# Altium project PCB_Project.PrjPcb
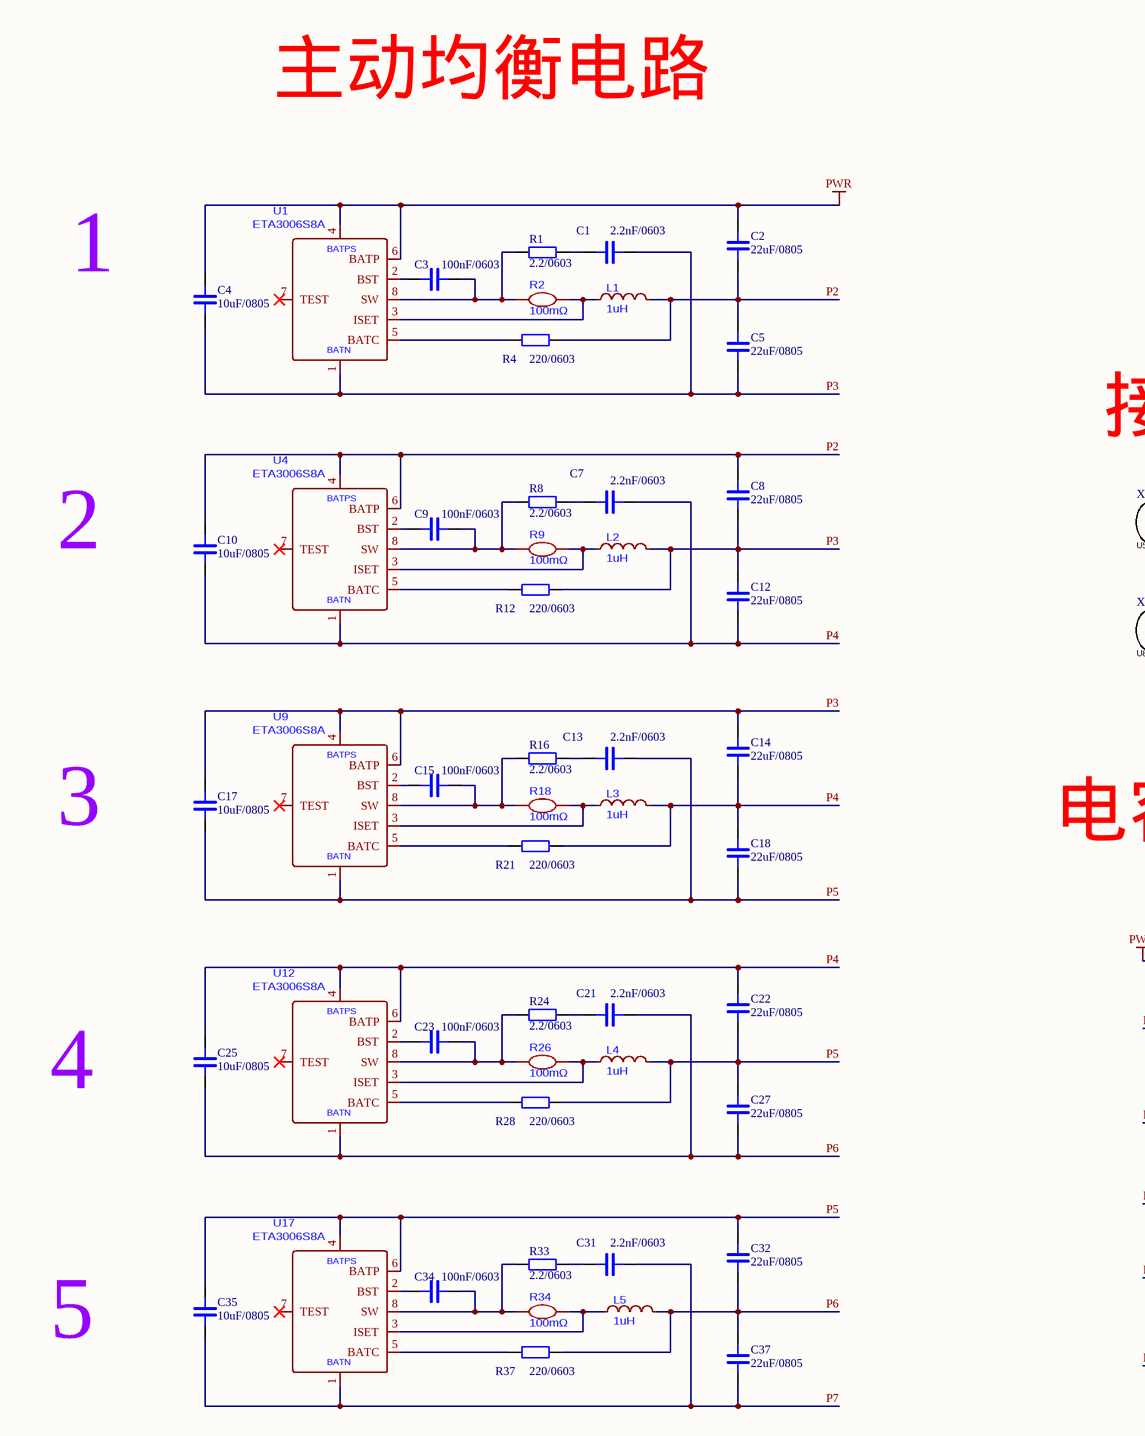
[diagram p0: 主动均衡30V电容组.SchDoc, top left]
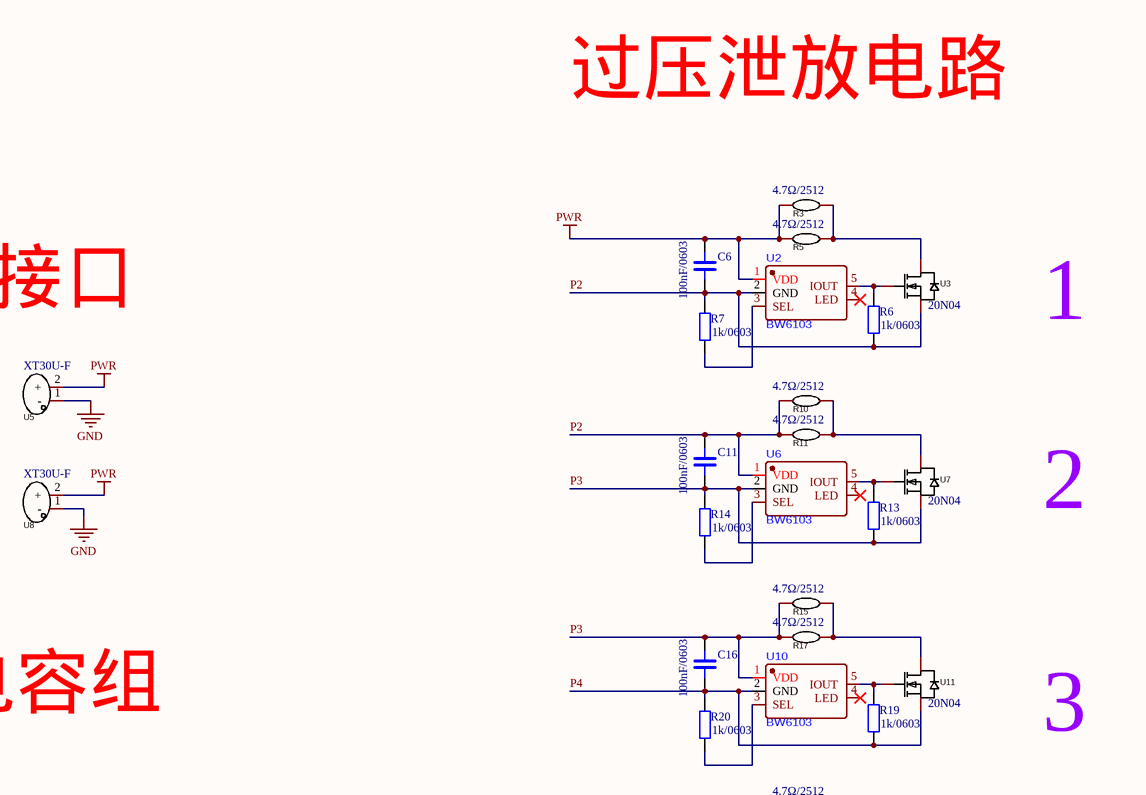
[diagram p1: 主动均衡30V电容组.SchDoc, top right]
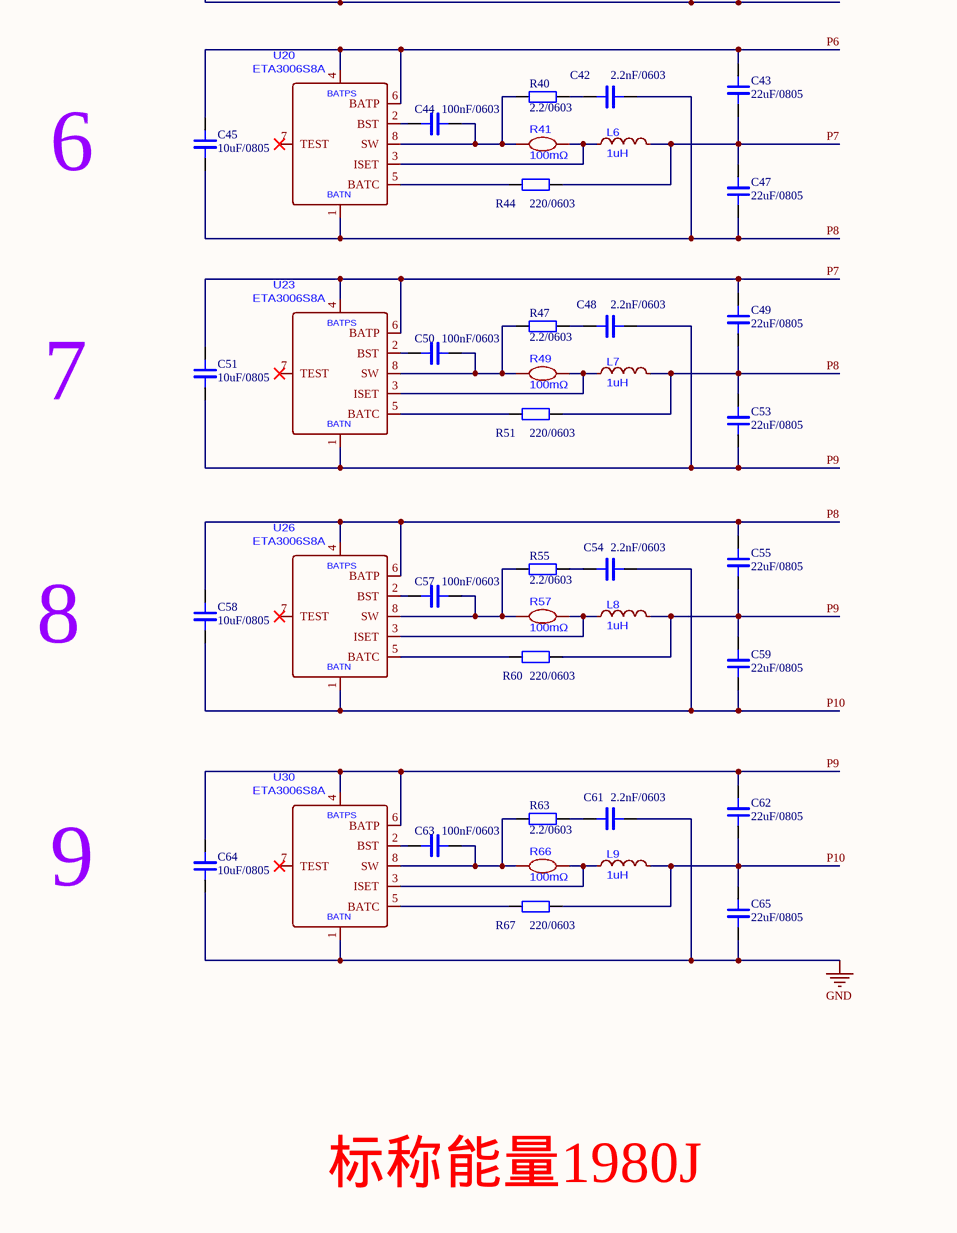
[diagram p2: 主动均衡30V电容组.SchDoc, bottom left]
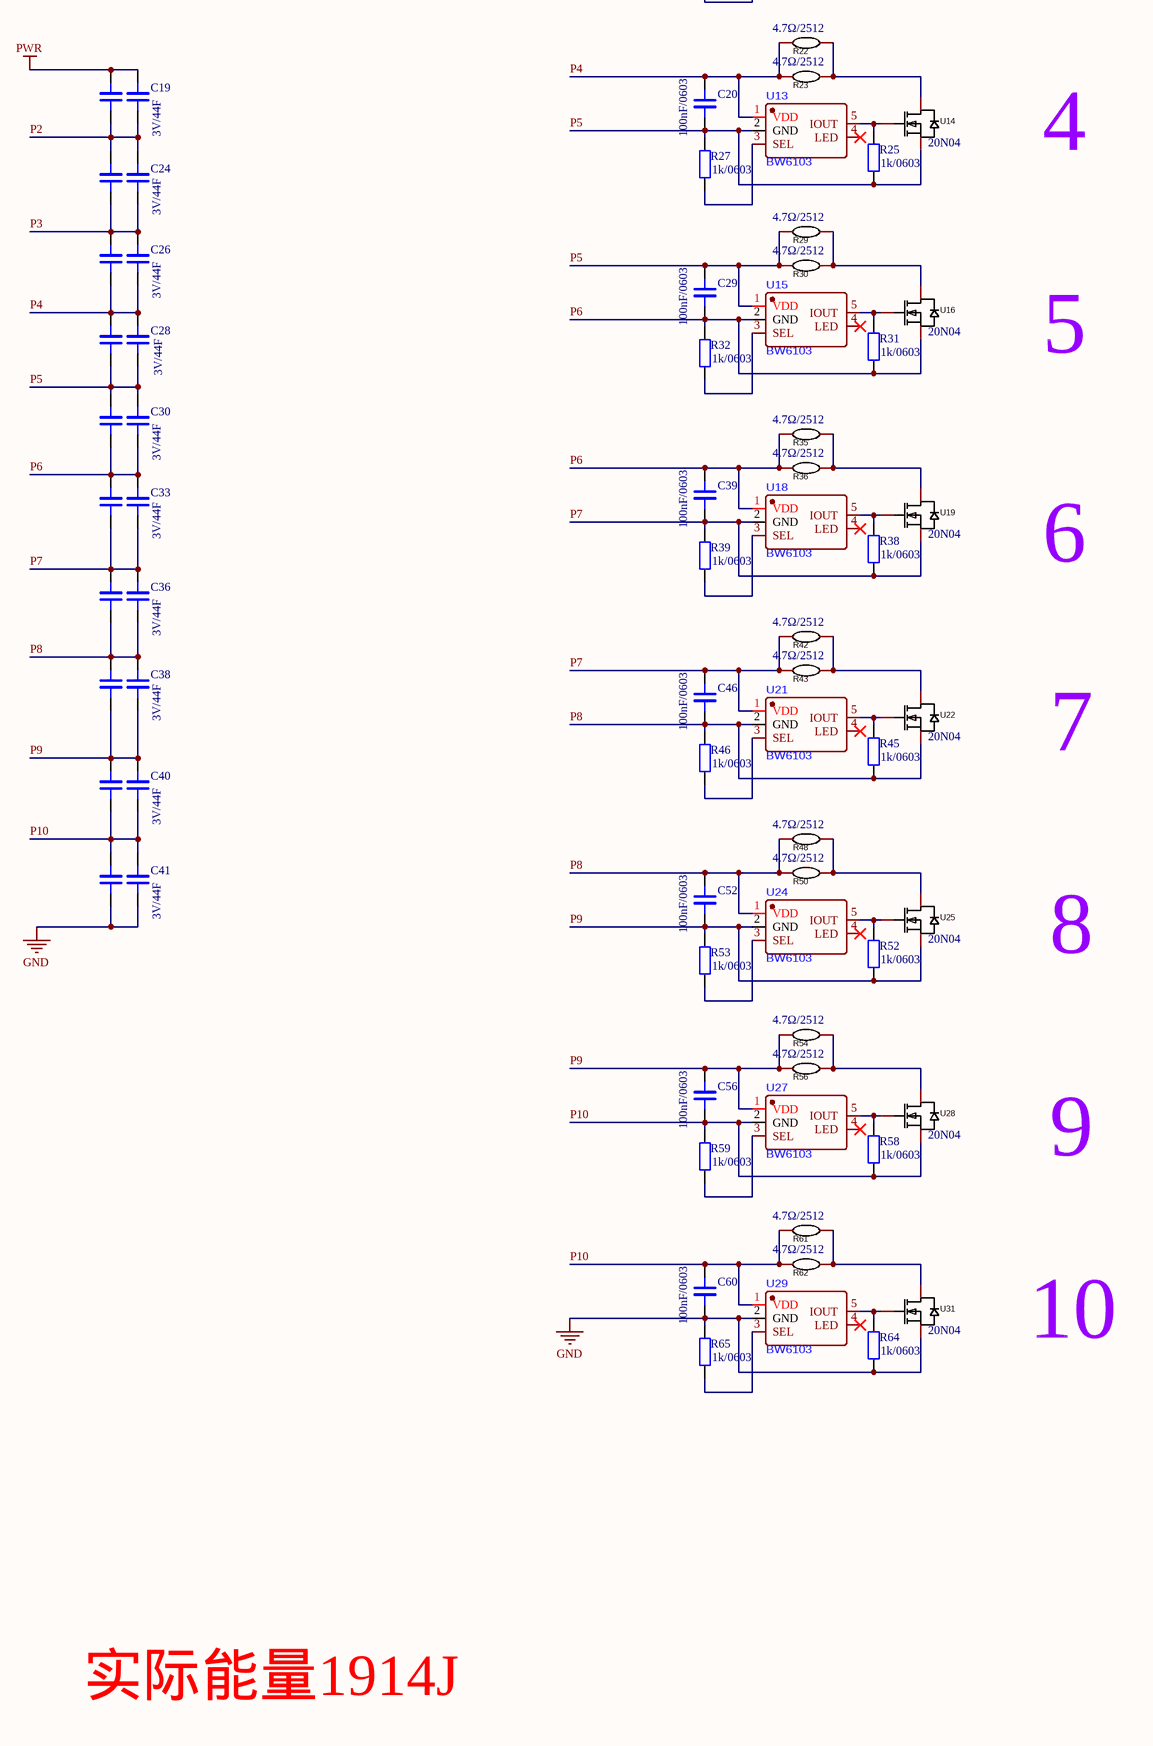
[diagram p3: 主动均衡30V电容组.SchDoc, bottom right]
1 sheet, 172 parts. Net scope: global (net labels, ports and power ports of the same name join across sheets).
Board file: PCB.PcbDoc

## Sheet 主动均衡30V电容组.SchDoc
size A1; SheetNumber: 1; SheetTotal: 1

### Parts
C1  2.2nF/0603  [C 0603_L]
C2  22uF/0805  [C 0805_L]
C3  100nF/0603  [C 0603_L]
C4  10uF/0805  [C 0805_L]
C5  22uF/0805  [C 0805_L]
C6  100nF/0603  [C 0603_L]
C7  2.2nF/0603  [C 0603_L]
C8  22uF/0805  [C 0805_L]
C9  100nF/0603  [C 0603_L]
C10  10uF/0805  [C 0805_L]
C11  100nF/0603  [C 0603_L]
C12  22uF/0805  [C 0805_L]
C13  2.2nF/0603  [C 0603_L]
C14  22uF/0805  [C 0805_L]
C15  100nF/0603  [C 0603_L]
C16  100nF/0603  [C 0603_L]
C17  10uF/0805  [C 0805_L]
C18  22uF/0805  [C 0805_L]
C19  3V/44F  [cap]
C20  100nF/0603  [C 0603_L]
C21  2.2nF/0603  [C 0603_L]
C22  22uF/0805  [C 0805_L]
C23  100nF/0603  [C 0603_L]
C24  3V/44F  [cap]
C25  10uF/0805  [C 0805_L]
C26  3V/44F  [cap]
C27  22uF/0805  [C 0805_L]
C28  3V/44F  [cap]
C29  100nF/0603  [C 0603_L]
C30  3V/44F  [cap]
C31  2.2nF/0603  [C 0603_L]
C32  22uF/0805  [C 0805_L]
C33  3V/44F  [cap]
C34  100nF/0603  [C 0603_L]
C35  10uF/0805  [C 0805_L]
C36  3V/44F  [cap]
C37  22uF/0805  [C 0805_L]
C38  3V/44F  [cap]
C39  100nF/0603  [C 0603_L]
C40  3V/44F  [cap]
C41  3V/44F  [cap]
C42  2.2nF/0603  [C 0603_L]
C43  22uF/0805  [C 0805_L]
C44  100nF/0603  [C 0603_L]
C45  10uF/0805  [C 0805_L]
C46  100nF/0603  [C 0603_L]
C47  22uF/0805  [C 0805_L]
C48  2.2nF/0603  [C 0603_L]
C49  22uF/0805  [C 0805_L]
C50  100nF/0603  [C 0603_L]
C51  10uF/0805  [C 0805_L]
C52  100nF/0603  [C 0603_L]
C53  22uF/0805  [C 0805_L]
C54  2.2nF/0603  [C 0603_L]
C55  22uF/0805  [C 0805_L]
C56  100nF/0603  [C 0603_L]
C57  100nF/0603  [C 0603_L]
C58  10uF/0805  [C 0805_L]
C59  22uF/0805  [C 0805_L]
C60  100nF/0603  [C 0603_L]
C61  2.2nF/0603  [C 0603_L]
C62  22uF/0805  [C 0805_L]
C63  100nF/0603  [C 0603_L]
C64  10uF/0805  [C 0805_L]
C65  22uF/0805  [C 0805_L]
L1  1uH  [IND-SMD_L4.4-W4.2]
L2  1uH  [IND-SMD_L4.4-W4.2]
L3  1uH  [IND-SMD_L4.4-W4.2]
L4  1uH  [IND-SMD_L4.4-W4.2]
L5  1uH  [IND-SMD_L4.4-W4.2]
L6  1uH  [IND-SMD_L4.4-W4.2]
L7  1uH  [IND-SMD_L4.4-W4.2]
L8  1uH  [IND-SMD_L4.4-W4.2]
L9  1uH  [IND-SMD_L4.4-W4.2]
R1  2.2/0603  [R 0603_L]
R2  100mΩ  [RES-SMD_L6.4-W3.2-R2512]
R3  4.7Ω/2512  [R2512]
R4  220/0603  [R 0603_L]
R5  4.7Ω/2512  [R2512]
R6  1k/0603  [R 0603_L]
R7  1k/0603  [R 0603_L]
R8  2.2/0603  [R 0603_L]
R9  100mΩ  [RES-SMD_L6.4-W3.2-R2512]
R10  4.7Ω/2512  [R2512]
R11  4.7Ω/2512  [R2512]
R12  220/0603  [R 0603_L]
R13  1k/0603  [R 0603_L]
R14  1k/0603  [R 0603_L]
R15  4.7Ω/2512  [R2512]
R16  2.2/0603  [R 0603_L]
R17  4.7Ω/2512  [R2512]
R18  100mΩ  [RES-SMD_L6.4-W3.2-R2512]
R19  1k/0603  [R 0603_L]
R20  1k/0603  [R 0603_L]
R21  220/0603  [R 0603_L]
R22  4.7Ω/2512  [R2512]
R23  4.7Ω/2512  [R2512]
R24  2.2/0603  [R 0603_L]
R25  1k/0603  [R 0603_L]
R26  100mΩ  [RES-SMD_L6.4-W3.2-R2512]
R27  1k/0603  [R 0603_L]
R28  220/0603  [R 0603_L]
R29  4.7Ω/2512  [R2512]
R30  4.7Ω/2512  [R2512]
R31  1k/0603  [R 0603_L]
R32  1k/0603  [R 0603_L]
R33  2.2/0603  [R 0603_L]
R34  100mΩ  [RES-SMD_L6.4-W3.2-R2512]
R35  4.7Ω/2512  [R2512]
R36  4.7Ω/2512  [R2512]
R37  220/0603  [R 0603_L]
R38  1k/0603  [R 0603_L]
R39  1k/0603  [R 0603_L]
R40  2.2/0603  [R 0603_L]
R41  100mΩ  [RES-SMD_L6.4-W3.2-R2512]
R42  4.7Ω/2512  [R2512]
R43  4.7Ω/2512  [R2512]
R44  220/0603  [R 0603_L]
R45  1k/0603  [R 0603_L]
R46  1k/0603  [R 0603_L]
R47  2.2/0603  [R 0603_L]
R48  4.7Ω/2512  [R2512]
R49  100mΩ  [RES-SMD_L6.4-W3.2-R2512]
R50  4.7Ω/2512  [R2512]
R51  220/0603  [R 0603_L]
R52  1k/0603  [R 0603_L]
R53  1k/0603  [R 0603_L]
R54  4.7Ω/2512  [R2512]
R55  2.2/0603  [R 0603_L]
R56  4.7Ω/2512  [R2512]
R57  100mΩ  [RES-SMD_L6.4-W3.2-R2512]
R58  1k/0603  [R 0603_L]
R59  1k/0603  [R 0603_L]
R60  220/0603  [R 0603_L]
R61  4.7Ω/2512  [R2512]
R62  4.7Ω/2512  [R2512]
R63  2.2/0603  [R 0603_L]
R64  1k/0603  [R 0603_L]
R65  1k/0603  [R 0603_L]
R66  100mΩ  [RES-SMD_L6.4-W3.2-R2512]
R67  220/0603  [R 0603_L]
U1  ETA3006S8A  [SOIC-8_L5.0-W4.0-P1.27-LS6.0-TL]
U2  BW6103  [TSOT-23-5_L2.9-W1.6-P0.95-LS2.8-BL]
U3  20N04  [TO-252-2_L6.6-W6.1-P4.57-LS9.9-BR-CW]
U4  ETA3006S8A  [SOIC-8_L5.0-W4.0-P1.27-LS6.0-TL]
U5  XT30U-F  [CONN-TH_XT30U-F]
U6  BW6103  [TSOT-23-5_L2.9-W1.6-P0.95-LS2.8-BL]
U7  20N04  [TO-252-2_L6.6-W6.1-P4.57-LS9.9-BR-CW]
U8  XT30U-F  [CONN-TH_XT30U-F]
U9  ETA3006S8A  [SOIC-8_L5.0-W4.0-P1.27-LS6.0-TL]
U10  BW6103  [TSOT-23-5_L2.9-W1.6-P0.95-LS2.8-BL]
U11  20N04  [TO-252-2_L6.6-W6.1-P4.57-LS9.9-BR-CW]
U12  ETA3006S8A  [SOIC-8_L5.0-W4.0-P1.27-LS6.0-TL]
U13  BW6103  [TSOT-23-5_L2.9-W1.6-P0.95-LS2.8-BL]
U14  20N04  [TO-252-2_L6.6-W6.1-P4.57-LS9.9-BR-CW]
U15  BW6103  [TSOT-23-5_L2.9-W1.6-P0.95-LS2.8-BL]
U16  20N04  [TO-252-2_L6.6-W6.1-P4.57-LS9.9-BR-CW]
U17  ETA3006S8A  [SOIC-8_L5.0-W4.0-P1.27-LS6.0-TL]
U18  BW6103  [TSOT-23-5_L2.9-W1.6-P0.95-LS2.8-BL]
U19  20N04  [TO-252-2_L6.6-W6.1-P4.57-LS9.9-BR-CW]
U20  ETA3006S8A  [SOIC-8_L5.0-W4.0-P1.27-LS6.0-TL]
U21  BW6103  [TSOT-23-5_L2.9-W1.6-P0.95-LS2.8-BL]
U22  20N04  [TO-252-2_L6.6-W6.1-P4.57-LS9.9-BR-CW]
U23  ETA3006S8A  [SOIC-8_L5.0-W4.0-P1.27-LS6.0-TL]
U24  BW6103  [TSOT-23-5_L2.9-W1.6-P0.95-LS2.8-BL]
U25  20N04  [TO-252-2_L6.6-W6.1-P4.57-LS9.9-BR-CW]
U26  ETA3006S8A  [SOIC-8_L5.0-W4.0-P1.27-LS6.0-TL]
U27  BW6103  [TSOT-23-5_L2.9-W1.6-P0.95-LS2.8-BL]
U28  20N04  [TO-252-2_L6.6-W6.1-P4.57-LS9.9-BR-CW]
U29  BW6103  [TSOT-23-5_L2.9-W1.6-P0.95-LS2.8-BL]
U30  ETA3006S8A  [SOIC-8_L5.0-W4.0-P1.27-LS6.0-TL]
U31  20N04  [TO-252-2_L6.6-W6.1-P4.57-LS9.9-BR-CW]

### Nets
GND: C41.1 C41.3 C60.2 C61.1 C64.2 C65.2 R64.2 R65.1 U5.1(-) U8.1(-) U29.2(GND) U30.1(BATC) U31.3(S)
PWR: C2.1 C4.1 C6.1 C19.1 C19.3 R3.1 R5.1 U1.4(BATPS) U1.6(BATP) U2.1(VDD) U5.2(+) U8.2(+)
P2: C2.2 C5.1 C6.2 C8.1 C10.1 C11.1 C19.2 C19.4 C24.2 C24.4 L1.2 R4.2 R6.2 R7.1 R10.1 R11.1 U2.2(GND) U3.3(S) U4.4(BATPS) U4.6(BATP) U6.1(VDD)
P3: C1.1 C4.2 C5.2 C8.2 C11.2 C12.1 C14.1 C16.1 C17.1 C24.1 C24.3 C26.1 C26.3 L2.2 R12.2 R13.2 R14.1 R15.1 R17.1 U1.1(BATC) U6.2(GND) U7.3(S) U9.4(BATPS) U9.6(BATP) U10.1(VDD)
P4: C7.1 C10.2 C12.2 C14.2 C16.2 C18.1 C20.1 C22.1 C25.1 C26.2 C26.4 C28.2 C28.4 L3.2 R19.2 R20.1 R21.2 R22.1 R23.1 U4.1(BATC) U10.2(GND) U11.3(S) U12.4(BATPS) U12.6(BATP) U13.1(VDD)
P5: C13.1 C17.2 C18.2 C20.2 C22.2 C27.1 C28.1 C28.3 C29.1 C30.1 C30.3 C32.1 C35.1 L4.2 R25.2 R27.1 R28.2 R29.1 R30.1 U9.1(BATC) U13.2(GND) U14.3(S) U15.1(VDD) U17.4(BATPS) U17.6(BATP)
P6: C21.1 C25.2 C27.2 C29.2 C30.2 C30.4 C32.2 C33.2 C33.4 C37.1 C39.1 C43.1 C45.1 L5.2 R31.2 R32.1 R35.1 R36.1 R37.2 U12.1(BATC) U15.2(GND) U16.3(S) U18.1(VDD) U20.4(BATPS) U20.6(BATP)
P7: C31.1 C33.1 C33.3 C35.2 C36.1 C36.3 C37.2 C39.2 C43.2 C46.1 C47.1 C49.1 C51.1 L6.2 R38.2 R39.1 R42.1 R43.1 R44.2 U17.1(BATC) U18.2(GND) U19.3(S) U21.1(VDD) U23.4(BATPS) U23.6(BATP)
P8: C36.2 C36.4 C38.2 C38.4 C42.1 C45.2 C46.2 C47.2 C49.2 C52.1 C53.1 C55.1 C58.1 L7.2 R45.2 R46.1 R48.1 R50.1 R51.2 U20.1(BATC) U21.2(GND) U22.3(S) U24.1(VDD) U26.4(BATPS) U26.6(BATP)
P9: C38.1 C38.3 C40.1 C40.3 C48.1 C51.2 C52.2 C53.2 C55.2 C56.1 C59.1 C62.1 C64.1 L8.2 R52.2 R53.1 R54.1 R56.1 R60.2 U23.1(BATC) U24.2(GND) U25.3(S) U27.1(VDD) U30.4(BATPS) U30.6(BATP)
P10: C40.2 C40.4 C41.2 C41.4 C54.1 C56.2 C58.2 C59.2 C60.1 C62.2 C65.1 L9.2 R58.2 R59.1 R61.1 R62.1 R67.2 U26.1(BATC) U27.2(GND) U28.3(S) U29.1(VDD)
NetC1_2: C1.2 R1.2
NetC3_1: C3.1 R1.1 R2.1 U1.8(SW)
NetC3_2: C3.2 U1.2(BST)
NetC7_2: C7.2 R8.2
NetC9_1: C9.1 R8.1 R9.1 U4.8(SW)
NetC9_2: C9.2 U4.2(BST)
NetC13_2: C13.2 R16.2
NetC15_1: C15.1 R16.1 R18.1 U9.8(SW)
NetC15_2: C15.2 U9.2(BST)
NetC21_2: C21.2 R24.2
NetC23_1: C23.1 R24.1 R26.1 U12.8(SW)
NetC23_2: C23.2 U12.2(BST)
NetC31_2: C31.2 R33.2
NetC34_1: C34.1 R33.1 R34.1 U17.8(SW)
NetC34_2: C34.2 U17.2(BST)
NetC42_2: C42.2 R40.2
NetC44_1: C44.1 R40.1 R41.1 U20.8(SW)
NetC44_2: C44.2 U20.2(BST)
NetC48_2: C48.2 R47.2
NetC50_1: C50.1 R47.1 R49.1 U23.8(SW)
NetC50_2: C50.2 U23.2(BST)
NetC54_2: C54.2 R55.2
NetC57_1: C57.1 R55.1 R57.1 U26.8(SW)
NetC57_2: C57.2 U26.2(BST)
NetC61_2: C61.2 R63.2
NetC63_1: C63.1 R63.1 R66.1 U30.8(SW)
NetC63_2: C63.2 U30.2(BST)
NetL1_1: L1.1 R2.2 U1.3(ISET)
NetL2_1: L2.1 R9.2 U4.3(ISET)
NetL3_1: L3.1 R18.2 U9.3(ISET)
NetL4_1: L4.1 R26.2 U12.3(ISET)
NetL5_1: L5.1 R34.2 U17.3(ISET)
NetL6_1: L6.1 R41.2 U20.3(ISET)
NetL7_1: L7.1 R49.2 U23.3(ISET)
NetL8_1: L8.1 R57.2 U26.3(ISET)
NetL9_1: L9.1 R66.2 U30.3(ISET)
NetR3_2: R3.2 R5.2 U3.2(D)
NetR4_1: R4.1 U1.5(BATC)
NetR6_1: R6.1 U2.5(IOUT) U3.1(G)
NetR7_2: R7.2 U2.3(SEL)
NetR10_2: R10.2 R11.2 U7.2(D)
NetR12_1: R12.1 U4.5(BATC)
NetR13_1: R13.1 U6.5(IOUT) U7.1(G)
NetR14_2: R14.2 U6.3(SEL)
NetR15_2: R15.2 R17.2 U11.2(D)
NetR19_1: R19.1 U10.5(IOUT) U11.1(G)
NetR20_2: R20.2 U10.3(SEL)
NetR21_1: R21.1 U9.5(BATC)
NetR22_2: R22.2 R23.2 U14.2(D)
NetR25_1: R25.1 U13.5(IOUT) U14.1(G)
NetR27_2: R27.2 U13.3(SEL)
NetR28_1: R28.1 U12.5(BATC)
NetR29_2: R29.2 R30.2 U16.2(D)
NetR31_1: R31.1 U15.5(IOUT) U16.1(G)
NetR32_2: R32.2 U15.3(SEL)
NetR35_2: R35.2 R36.2 U19.2(D)
NetR37_1: R37.1 U17.5(BATC)
NetR38_1: R38.1 U18.5(IOUT) U19.1(G)
NetR39_2: R39.2 U18.3(SEL)
NetR42_2: R42.2 R43.2 U22.2(D)
NetR44_1: R44.1 U20.5(BATC)
NetR45_1: R45.1 U21.5(IOUT) U22.1(G)
NetR46_2: R46.2 U21.3(SEL)
NetR48_2: R48.2 R50.2 U25.2(D)
NetR51_1: R51.1 U23.5(BATC)
NetR52_1: R52.1 U24.5(IOUT) U25.1(G)
NetR53_2: R53.2 U24.3(SEL)
NetR54_2: R54.2 R56.2 U28.2(D)
NetR58_1: R58.1 U27.5(IOUT) U28.1(G)
NetR59_2: R59.2 U27.3(SEL)
NetR60_1: R60.1 U26.5(BATC)
NetR61_2: R61.2 R62.2 U31.2(D)
NetR64_1: R64.1 U29.5(IOUT) U31.1(G)
NetR65_2: R65.2 U29.3(SEL)
NetR67_1: R67.1 U30.5(BATC)

Not connected (* = marked no-connect by the designer): U1 7(TEST)*; U2 4(LED)*; U4 7(TEST)*; U6 4(LED)*; U9 7(TEST)*; U10 4(LED)*; U12 7(TEST)*; U13 4(LED)*; U15 4(LED)*; U17 7(TEST)*; U18 4(LED)*; U20 7(TEST)*; U21 4(LED)*; U23 7(TEST)*; U24 4(LED)*; U26 7(TEST)*; U27 4(LED)*; U29 4(LED)*; U30 7(TEST)*

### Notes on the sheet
- 主动均衡电路
- 过压泄放电路
- 1
- 接口
- 2
- 3
- 电容组
- 4
- 5
- 6
- 7
- 8
- 9
- 10
- 标称能量1980J
- 实际能量1914J

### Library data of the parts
C1-C18 C20-C23 C25 C27 C29 C31 C32 C34 C35 C37 C39 C42-C65 = CAP: 陶瓷电容
C19 C24 C26 C28 C30 C33 C36 C38 C40 C41 = 3V 44F: 3V 40F 超级电容
L1-L9 = FXL0420-1R0-M
R1 R4 R6-R8 R12-R14 R16 R19-R21 R24 R25 R27 R28 R31-R33 R37-R40 R44-R47 R51-R53 R55 R58-R60 R63-R65 R67 = RES: 贴片电阻
R2 R9 R18 R26 R34 R41 R49 R57 R66 = HOJLR2512-3W-100MR-1%
R3 R5 R10 R11 R15 R17 R22 R23 R29 R30 R35 R36 R42 R43 R48 R50 R54 R56 R61 R62 = WF25P4R70FTL: 4.7Ω 2W; Manufacturer: Walsin(华新科); Add into BOM: yes; Tolerance: ±1%; Overload Voltage (Max): 300V; Temperature Coefficient: ±100ppm/℃
U2 U6 U10 U13 U15 U18 U21 U24 U27 U29 = BW6103: 3V 均压保护芯片
U3 U7 U11 U14 U16 U19 U22 U25 U28 U31 = 20N04: 40V 20A; Manufacturer: HL(富海微); Add into BOM: yes; Drain Source On Resistance (RDS(on)@Vgs,Id): 25mΩ; Gate Threshold Voltage (Vgs(th)@Id): 2.2V
U5 U8 = XT30U-F: Manufacturer: AMASS(艾迈斯); Add into BOM: yes; Brand: 艾迈斯; InterfaceType: 母头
